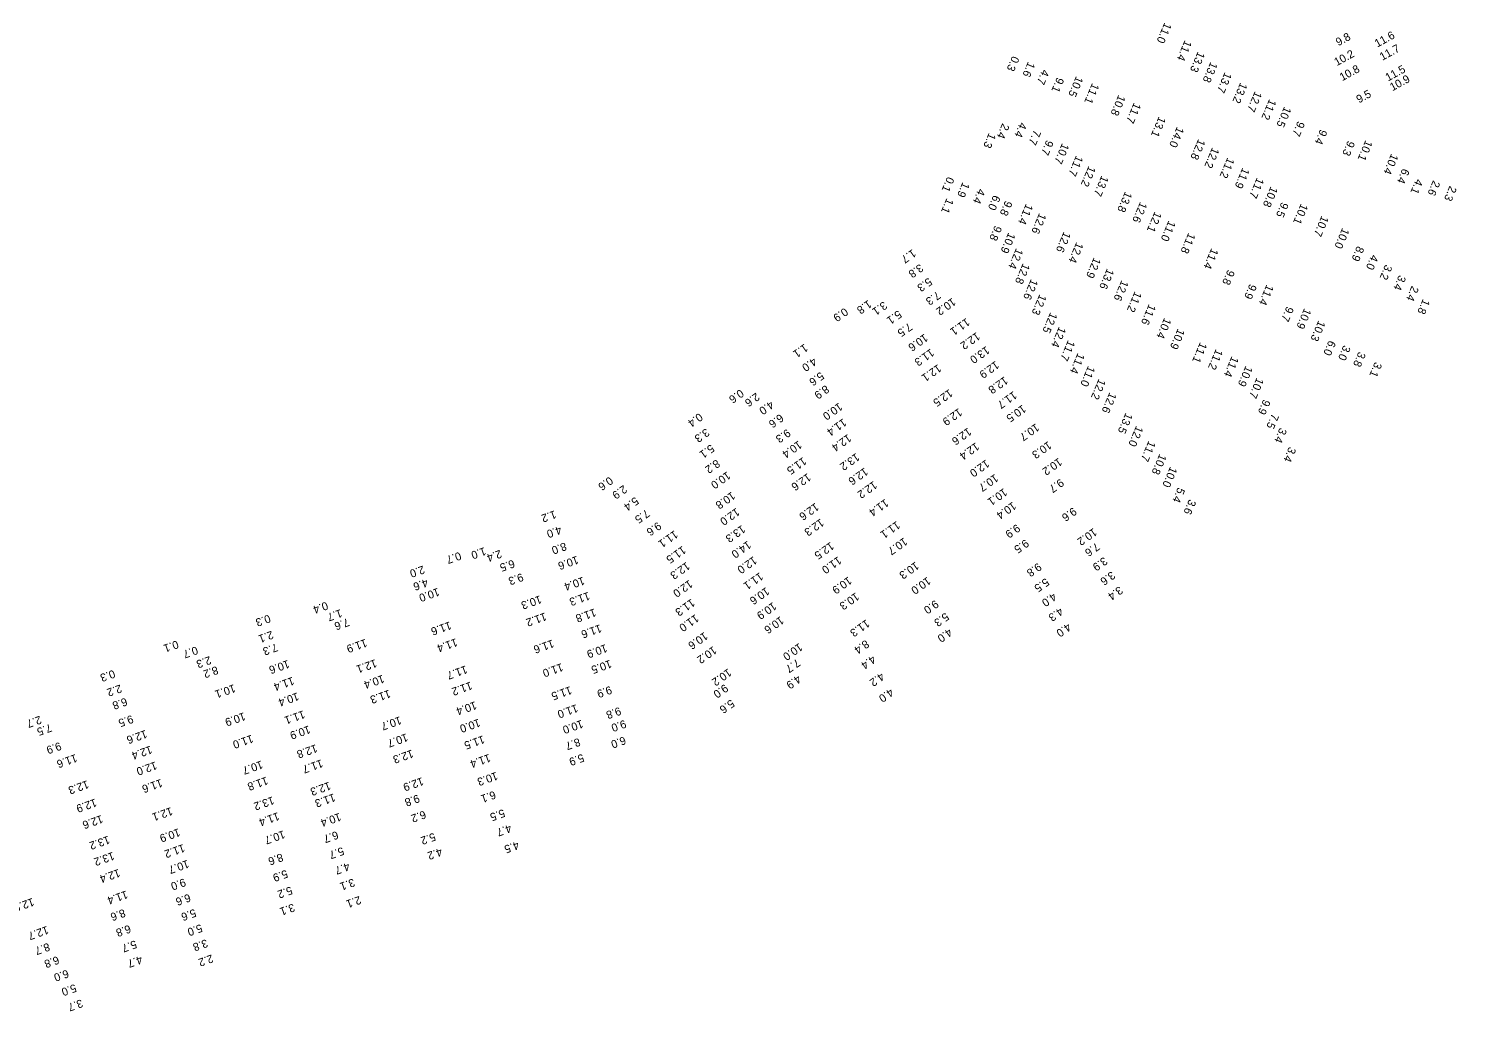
# Model space of a CAD drawing. Extents: x 815385 to 820851, y 582449 to 604245.
# Drawn here: x 817257 to 818150, y 599658 to 600273 of the extents above; entities that cross this region are included whole.
import ezdxf

# ---------------------------------------------------------------- set-up
doc = ezdxf.new("R2010")
doc.units = 0
doc.layers.add('V-TOPO-SOUN-021909', color=7, linetype='Continuous')
doc.layers.add('V-TOPO-SOUN-022409', color=7, linetype='Continuous')

msp = doc.modelspace()

# ---------------------------------------------------------------- texts
at = {"layer": 'V-TOPO-SOUN-021909'}
for s, rotation, p in [('11.0 ', 246.933, (817967.27, 600276.69)), ('11.4 ', 246.933, (817979.92, 600265.64)), ('0.3', 246.933, (817872.11, 600255.81)), ('13.3 ', 246.933, (817988.1, 600258.56)), ('1.6', 246.933, (817881.99, 600252.18)), ('4.7', 246.933, (817890.89, 600247.45)), ('13.8 ', 246.933, (817996.04, 600252.1)), ('13.7 ', 246.933, (818004.9, 600245.63)), ('9.1', 246.933, (817900.08, 600242.54)), ('10.5 ', 246.933, (817912.05, 600243.17)), ('11.1 ', 246.933, (817922.07, 600238.81)), ('13.2 ', 246.933, (818014.63, 600239.16)), ('10.8 ', 246.933, (817938.49, 600231.42)), ('12.7 ', 246.933, (818023.74, 600233.75)), ('11.2 ', 246.933, (818032.75, 600228.85)), ('11.7 ', 246.933, (817948.18, 600226.62)), ('10.5 ', 246.933, (818042.1, 600224.19)), ('2.4', 246.933, (817865.93, 600213.68)), ('4.4', 246.933, (817876.9, 600214.43)), ('13.1 ', 246.933, (817963.71, 600217.97)), ('14.0 ', 246.933, (817975.06, 600211.58)), ('9.7', 246.933, (818050.52, 600215.09)), ('9.4', 246.933, (818064.54, 600210)), ('1.3', 246.933, (817857.52, 600207.72)), ('7.7', 246.933, (817885.69, 600209.65)), ('9.7', 246.933, (817893.47, 600203.31)), ('10.7 ', 246.933, (817903.28, 600201.27)), ('12.8 ', 246.933, (817988.38, 600203.88)), ('9.3', 246.933, (818081.8, 600202.92)), ('10.1 ', 246.933, (818092.86, 600203.17)), ('11.7 ', 246.933, (817912.05, 600193.59)), ('12.2 ', 246.933, (817997.1, 600198.63)), ('11.2 ', 246.933, (818006.61, 600192.34)), ('10.4 ', 246.933, (818108.96, 600194.73)), ('12.2 ', 246.933, (817919.85, 600187.06)), ('11.9 ', 246.933, (818016.02, 600185.92)), ('6.4', 246.933, (818115.98, 600185.54)), ('0.1', 246.933, (817831.5, 600180.36)), ('1.9', 246.933, (817841.11, 600176.95)), ('13.7 ', 246.933, (817927.92, 600181.02)), ('11.7 ', 246.933, (818025.04, 600179.75)), ('10.8 ', 246.933, (818033.64, 600174.25)), ('4.1', 246.933, (818124.41, 600179.03)), ('2.6', 246.933, (818135.1, 600178.03)), ('2.3', 246.933, (818145.44, 600174.65)), ('1.1', 246.933, (817831.11, 600166.89)), ('4.4', 246.933, (817850.93, 600172.96)), ('6.0', 246.933, (817860.38, 600168.89)), ('9.8', 246.933, (817867.77, 600165.46)), ('13.8 ', 246.933, (817942.67, 600171.07)), ('11.4 ', 246.933, (817880.72, 600163.43)), ('12.6 ', 246.933, (817888.99, 600157.6)), ('12.6 ', 246.933, (817952.05, 600164.59)), ('12.1 ', 246.933, (817961.14, 600158.53)), ('9.5', 246.933, (818040.38, 600164.46)), ('10.1 ', 246.933, (818052.53, 600163.53)), ('10.7 ', 246.933, (818065.42, 600155.92)), ('9.8', 246.933, (817861.22, 600149.86)), ('11.0 ', 246.933, (817969.83, 600152.92)), ('10.0 ', 246.933, (818078.37, 600148.33)), ('10.9 ', 246.933, (817869.74, 600145.43)), ('12.6 ', 246.933, (817904.33, 600145.99)), ('12.4 ', 246.933, (817912.18, 600139.39)), ('11.8 ', 246.933, (817982.23, 600145.27)), ('1.7', 215.121, (817809.75, 600134.98)), ('12.4 ', 246.933, (817874.56, 600135.63)), ('12.9 ', 246.933, (817923.13, 600129.88)), ('11.4 ', 246.933, (817996.54, 600135.63)), ('8.9', 246.933, (818087.59, 600137.02)), ('4.0', 246.933, (818096.58, 600131.68)), ('3.8', 215.121, (817814.31, 600125.79)), ('12.8 ', 246.933, (817878.77, 600126.22)), ('13.6 ', 246.933, (817931.36, 600122.93)), ('9.8', 246.933, (818006.75, 600122.24)), ('3.2', 246.933, (818105.17, 600125.44)), ('5.3', 215.121, (817819.77, 600117.17)), ('12.6 ', 246.933, (817883.86, 600116.42)), ('12.6 ', 246.933, (817940.4, 600115.67)), ('9.9', 246.933, (818020.47, 600113.36)), ('11.4 ', 246.933, (818031.06, 600112.95)), ('3.4', 246.933, (818113.74, 600118.86)), ('2.4', 246.933, (818121.75, 600112.14)), ('1.8', 215.121, (817782.04, 600103.2)), ('7.3', 215.121, (817825.12, 600108.72)), ('10.2 ', 215.121, (817834.62, 600104.56)), ('12.3 ', 246.933, (817889.17, 600106.86)), ('11.2 ', 246.933, (817948.68, 600108.64)), ('1.8', 246.933, (818128.75, 600103.94)), ('0.9', 215.121, (817767.27, 600098.4)), ('3.1', 215.121, (817791.69, 600102.35)), ('5.1', 215.121, (817800.76, 600096.79)), ('12.5 ', 246.933, (817895.91, 600095.54)), ('11.6 ', 246.933, (817957.51, 600100.68)), ('9.7', 246.933, (818043.58, 600099.32)), ('10.9 ', 246.933, (818054.59, 600098.15)), ('7.5', 215.121, (817807.39, 600089)), ('11.1 ', 215.121, (817843.37, 600091.94)), ('12.4 ', 246.933, (817901.32, 600086.6)), ('10.4 ', 246.933, (817967.12, 600092.17)), ('10.9 ', 246.933, (817975.56, 600085.4)), ('10.3 ', 246.933, (818063.41, 600090.45)), ('1.1', 215.121, (817742.2, 600075.84)), ('10.6 ', 215.121, (817817.18, 600082.1)), ('12.2 ', 215.121, (817849.79, 600083.14)), ('11.7 ', 246.933, (817906.98, 600078.17)), ('11.1 ', 246.933, (817989.48, 600076.88)), ('6.0', 246.933, (818069.95, 600078.08)), ('4.0', 215.121, (817747.75, 600067.3)), ('11.3 ', 215.121, (817821.1, 600072.84)), ('13.0 ', 215.121, (817855.75, 600074.37)), ('11.4 ', 246.933, (817913.03, 600070.15)), ('11.2 ', 246.933, (817999.36, 600072.64)), ('11.4 ', 246.933, (818009.25, 600068.11)), ('3.0', 246.933, (818079.14, 600075.04)), ('3.8', 246.933, (818088.56, 600071.02)), ('5.6', 215.121, (817752.25, 600058.32)), ('12.1 ', 215.121, (817825.6, 600063.06)), ('12.9 ', 215.121, (817861.65, 600065.13)), ('11.0 ', 246.933, (817919.56, 600062.14)), ('10.9 ', 246.933, (818017.95, 600062.13)), ('3.1', 246.933, (818098.73, 600064.58)), ('8.9', 215.121, (817755.45, 600050.04)), ('12.8 ', 215.121, (817867.22, 600055.46)), ('12.2 ', 246.933, (817926.18, 600054.03)), ('10.7 ', 246.933, (818024.87, 600054.76)), ('0.6', 215.121, (817702.11, 600047.46)), ('2.6', 215.121, (817712.03, 600045.27)), ('12.5 ', 215.121, (817832.7, 600047.54)), ('11.7 ', 215.121, (817872.82, 600046.22)), ('12.6 ', 246.933, (817932.92, 600045.57)), ('9.9', 246.933, (818029.03, 600041.18)), ('0.4', 215.121, (817676.46, 600032.63)), ('4.0', 215.121, (817720.98, 600040.28)), ('6.6', 215.121, (817726.98, 600032.06)), ('10.0 ', 215.121, (817763.8, 600039.04)), ('12.9 ', 215.121, (817838.6, 600035.6)), ('10.5 ', 215.121, (817878.5, 600037.77)), ('13.5 ', 246.933, (817942.97, 600032.76)), ('7.5', 246.933, (818034.36, 600032.33)), ('3.3', 215.121, (817680.64, 600022.97)), ('9.3', 215.121, (817731.35, 600022.67)), ('11.4 ', 215.121, (817766.36, 600029.18)), ('12.6 ', 215.121, (817844.41, 600023.44)), ('10.7 ', 215.121, (817886.77, 600026.09)), ('12.0 ', 246.933, (817949.58, 600024.65)), ('3.4', 246.933, (818039.29, 600023.48)), ('10.4 ', 215.121, (817738.47, 600015.32)), ('12.4 ', 215.121, (817769.38, 600019.43)), ('12.4 ', 215.121, (817849.26, 600014.22)), ('10.3 ', 215.121, (817894.51, 600014.93)), ('11.7 ', 246.933, (817957.33, 600015.3)), ('5.1', 215.121, (817683.71, 600013)), ('11.5 ', 215.121, (817741.33, 600005.03)), ('13.2 ', 215.121, (817774.47, 600007.55)), ('10.2 ', 215.121, (817901.04, 600004.57)), ('10.8 ', 246.933, (817964.13, 600007.09)), ('3.4', 246.933, (818045.03, 600011.54)), ('8.2', 215.121, (817687.23, 600003.56)), ('10.0 ', 215.121, (817693.88, 599996.07)), ('12.6 ', 215.121, (817779.78, 599998.47)), ('12.0 ', 215.121, (817855.64, 600003.48)), ('10.0 ', 246.933, (817970.82, 599999.14)), ('0.6', 215.121, (817620.4, 599992.89)), ('2.9', 215.121, (817629.17, 599987.55)), ('12.6 ', 215.121, (817744.14, 599994.96)), ('12.2 ', 215.121, (817785.45, 599990.1)), ('10.7 ', 215.121, (817861.17, 599994.44)), ('9.7', 215.121, (817902.13, 599991.57)), ('5.4', 215.121, (817636.45, 599980.2)), ('10.8 ', 215.121, (817696.79, 599983.45)), ('11.4 ', 215.121, (817792.65, 599978.89)), ('10.1 ', 215.121, (817866.77, 599985.6)), ('5.4', 246.933, (817975.64, 599986.2)), ('3.6', 246.933, (817982.61, 599978.77)), ('1.2', 199.431, (817586.09, 599971.6)), ('7.5', 215.121, (817643.31, 599972.39)), ('12.0 ', 215.121, (817699.58, 599973.26)), ('12.6 ', 215.121, (817749.06, 599976.43)), ('10.4 ', 215.121, (817872.33, 599977.1)), ('9.6', 215.121, (817910.11, 599973.65)), ('4.0', 199.431, (817589.44, 599961.85)), ('9.6', 215.121, (817650.61, 599964.57)), ('13.3 ', 215.121, (817703.1, 599962.55)), ('12.3 ', 215.121, (817752.25, 599966.6)), ('11.1 ', 215.121, (817799.82, 599965.06)), ('9.9', 215.121, (817874.81, 599963.18)), ('10.2 ', 215.121, (817922.83, 599960.69)), ('8.0', 199.431, (817592.54, 599951.61)), ('11.1 ', 215.121, (817661.03, 599959.27)), ('14.0 ', 215.121, (817706.73, 599952.75)), ('12.5 ', 215.121, (817758.53, 599952.03)), ('10.7 ', 215.121, (817804.4, 599954.79)), ('9.5', 215.121, (817880.28, 599953.72)), ('7.6', 215.121, (817924.51, 599951.65)), ('0.7', 199.431, (817526.7, 599945.71)), ('1.0', 199.431, (817542.23, 599948.59)), ('2.4', 199.431, (817552.03, 599946.93)), ('10.6 ', 199.431, (817600.02, 599943.15)), ('11.5 ', 215.121, (817665.98, 599949.5)), ('12.0 ', 215.121, (817710.37, 599943.05)), ('11.0 ', 215.121, (817763.21, 599943)), ('3.9', 215.121, (817929.36, 599942.63)), ('2.0', 199.431, (817503.87, 599937.08)), ('6.5', 199.431, (817560.14, 599940.85)), ('12.3 ', 215.121, (817668.48, 599939.53)), ('11.1 ', 215.121, (817714.27, 599933.03)), ('10.3 ', 215.121, (817811.61, 599939.66)), ('9.8', 215.121, (817888.18, 599938.98)), ('3.6', 215.121, (817934.19, 599933.69)), ('4.6', 199.431, (817506.04, 599928.95)), ('9.3', 199.431, (817565.54, 599932.4)), ('10.4 ', 199.431, (817603.87, 599930.11)), ('12.0 ', 215.121, (817670.21, 599928.31)), ('10.6 ', 215.121, (817718.14, 599923.73)), ('10.9 ', 215.121, (817769.65, 599930.36)), ('10.0 ', 215.121, (817819, 599930.17)), ('5.5', 215.121, (817892.94, 599929.44)), ('3.4', 215.121, (817938.93, 599924.37)), ('10.0 ', 199.431, (817513.16, 599923.15)), ('10.3 ', 199.431, (817576.98, 599918.46)), ('11.3 ', 199.431, (817607.15, 599920.65)), ('11.3 ', 215.121, (817671.59, 599916.56)), ('10.3 ', 215.121, (817774.24, 599920.43)), ('9.0', 215.121, (817823.86, 599915.77)), ('4.0', 215.121, (817897.6, 599920.33)), ('0.3', 199.431, (817407.54, 599906.5)), ('0.4', 199.431, (817443.46, 599914.57)), ('1.7', 199.431, (817452.31, 599909.85)), ('11.2 ', 199.431, (817580.06, 599907.73)), ('11.8 ', 199.431, (817611.02, 599910.31)), ('11.0 ', 215.121, (817674.06, 599906.83)), ('10.9 ', 215.121, (817722.53, 599914.42)), ('5.3', 215.121, (817830.33, 599907.85)), ('4.3', 215.121, (817901.79, 599911.13)), ('7.6', 199.431, (817456.75, 599904.23)), ('11.6 ', 199.431, (817520.61, 599902.17)), ('11.6 ', 199.431, (817614.49, 599900.37)), ('10.6 ', 215.121, (817727.21, 599905.57)), ('11.3 ', 215.121, (817780.83, 599903.6)), ('4.0', 215.121, (817832.42, 599898.04)), ('4.0', 215.121, (817906.69, 599901.36)), ('0.1', 199.431, (817350.05, 599890.35)), ('2.1', 199.431, (817409.34, 599896.33)), ('7.3', 199.431, (817412.08, 599888.48)), ('11.9 ', 199.431, (817467.9, 599891.27)), ('11.4 ', 199.431, (817524.42, 599891.63)), ('11.6 ', 199.431, (817584.72, 599890.87)), ('10.9 ', 199.431, (817617.99, 599887.99)), ('10.6 ', 215.121, (817679.65, 599895.74)), ('10.0 ', 215.121, (817738.88, 599888.82)), ('8.4', 215.121, (817780.41, 599890.8)), ('0.7', 199.431, (817362.19, 599886.69)), ('2.3', 199.431, (817370.53, 599880.51)), ('10.2 ', 215.121, (817685.2, 599886.87)), ('4.4', 215.121, (817784.66, 599881.17)), ('0.3', 199.431, (817310.44, 599871.96)), ('8.2', 199.431, (817374.85, 599874.27)), ('10.6 ', 199.431, (817419.42, 599878.11)), ('12.1 ', 199.431, (817474, 599878.57)), ('11.7 ', 199.431, (817530.58, 599874.67)), ('11.0 ', 199.431, (817590.43, 599876.09)), ('10.5 ', 199.431, (817620.76, 599878.19)), ('10.2 ', 215.121, (817694.48, 599872.9)), ('7.7', 215.121, (817737.43, 599879.05)), ('2.2', 199.431, (817314.64, 599862.76)), ('10.1 ', 199.431, (817385.68, 599862.93)), ('11.4 ', 199.431, (817422.36, 599867.54)), ('10.4 ', 199.431, (817478.7, 599868.82)), ('11.2 ', 199.431, (817533.61, 599864.55)), ('11.5 ', 199.431, (817595.85, 599861.7)), ('9.9', 199.431, (817620.85, 599861.89)), ('9.0', 215.121, (817692.37, 599863.19)), ('4.9', 215.121, (817737.97, 599868.87)), ('4.2', 215.121, (817790.04, 599870.44)), ('6.8', 199.431, (817318.06, 599854.58)), ('10.4 ', 199.431, (817425.29, 599857.8)), ('11.3 ', 199.431, (817482.65, 599859.5)), ('10.4 ', 199.431, (817536.39, 599852.27)), ('5.6', 215.121, (817696.28, 599853.59)), ('4.0', 215.121, (817795.77, 599860.56)), ('2.7', 199.431, (817264.46, 599843.23)), ('9.5', 199.431, (817321.82, 599843.71)), ('10.9 ', 199.431, (817391.93, 599845.41)), ('11.1 ', 199.431, (817429.08, 599846.61)), ('11.0 ', 199.431, (817599.68, 599850.42)), ('9.8', 199.431, (817626.57, 599848.71)), ('7.5', 199.431, (817270.89, 599838.25)), ('12.6 ', 199.431, (817330.45, 599834.38)), ('10.9 ', 199.431, (817432.49, 599837.15)), ('10.7 ', 199.431, (817489.42, 599842.88)), ('10.0 ', 199.431, (817538.65, 599841.38)), ('10.0 ', 199.431, (817602.93, 599840.67)), ('9.0', 199.431, (817629.8, 599840.68)), ('9.9', 199.431, (817276.83, 599826.82)), ('11.0 ', 199.431, (817396.81, 599831.41)), ('12.8 ', 199.431, (817436.82, 599825.39)), ('10.7 ', 199.431, (817493.42, 599832.23)), ('11.5 ', 199.431, (817541.37, 599830.95)), ('8.7', 199.431, (817601.13, 599829.35)), ('6.0', 199.431, (817629.61, 599830.38)), ('11.6 ', 199.431, (817286.77, 599819.31)), ('12.4 ', 199.431, (817333.6, 599824.57)), ('12.3 ', 199.431, (817496.88, 599822.09)), ('11.4 ', 199.431, (817545.11, 599819.37)), ('5.9', 199.431, (817603.45, 599819.47)), ('12.0 ', 199.431, (817336.61, 599814.68)), ('10.7 ', 199.431, (817402.79, 599815.22)), ('11.7 ', 199.431, (817440.33, 599815.99)), ('10.3 ', 199.431, (817549.56, 599808.15)), ('12.3 ', 199.431, (817294.01, 599802.89)), ('11.6 ', 199.431, (817340.09, 599803.74)), ('11.8 ', 199.431, (817405.97, 599805.17)), ('12.3 ', 199.431, (817445.23, 599801.98)), ('12.9 ', 199.431, (817503.23, 599804.79)), ('12.9 ', 199.431, (817298.97, 599791.45)), ('13.2 ', 199.431, (817409.87, 599792.86)), ('11.3 ', 199.431, (817448.11, 599794.71)), ('9.8', 199.431, (817500.72, 599794.09)), ('6.1', 199.431, (817548.3, 599796.35)), ('12.6 ', 199.431, (817302.87, 599781.22)), ('12.1 ', 199.431, (817346.42, 599786.13)), ('11.4 ', 199.431, (817413.13, 599782.93)), ('10.4 ', 199.431, (817451.65, 599782.55)), ('6.2', 199.431, (817504.68, 599784.04)), ('5.5', 199.431, (817554.01, 599784.91)), ('10.9 ', 199.431, (817351.1, 599772.89)), ('4.7', 199.431, (817558.17, 599775.39)), ('13.2 ', 199.431, (817307.14, 599768.25)), ('11.2 ', 199.431, (817354.04, 599763.06)), ('10.7 ', 199.431, (817416.66, 599771.65)), ('6.7', 199.431, (817449.95, 599771.25)), ('5.2', 199.431, (817510.69, 599770.14)), ('4.5', 199.431, (817562.92, 599764.83)), ('13.2 ', 199.431, (817310.04, 599758.15)), ('8.6', 199.431, (817415.42, 599757.29)), ('5.7', 199.431, (817453.49, 599761.22)), ('4.2', 199.431, (817514.9, 599760.72)), ('12.4 ', 199.431, (817313.62, 599747.52)), ('10.7 ', 199.431, (817356.64, 599753.19)), ('5.9', 199.431, (817418.32, 599747)), ('4.7', 199.431, (817457.09, 599751.55)), ('9.0', 199.431, (817354.59, 599741.66)), ('5.2', 199.431, (817421.21, 599736.62)), ('3.1', 199.431, (817460.24, 599741.55)), ('12.9 ', 199.431, (817259.85, 599729.39)), ('11.4 ', 199.431, (817318.38, 599734.03)), ('6.6', 199.431, (817357.62, 599732.04)), ('2.1', 199.431, (817464.16, 599730.61)), ('8.6', 199.431, (817316.86, 599722.51)), ('5.6', 199.431, (817361.04, 599722.55)), ('3.1', 199.431, (817422.69, 599725.88)), ('12.7 ', 199.431, (817268.88, 599711.86)), ('6.8', 199.431, (817320.27, 599712.61)), ('5.0', 199.431, (817364.94, 599713.05)), ('8.7', 199.431, (817269.64, 599701.32)), ('5.7', 199.431, (817323.95, 599702.94)), ('3.8', 199.431, (817368.34, 599703.6)), ('6.8', 199.431, (817275.48, 599693.11)), ('4.7', 199.431, (817327.48, 599693.34)), ('2.2', 199.431, (817371.79, 599694.04)), ('6.0', 199.431, (817281.5, 599684.64)), ('5.0', 199.431, (817286.27, 599675.61)), ('3.7', 199.431, (817290.29, 599666.06))]:
    msp.add_text(s, height=5, rotation=rotation, dxfattribs=at).set_placement(p)
at = {"layer": 'V-TOPO-SOUN-022409'}
for s, p in [('9.8', (818075.86, 600261.53)), ('11.6 ', (818100.17, 600260.7)), ('11.7 ', (818103.31, 600252.44)), ('10.2 ', (818074.87, 600249.08)), ('10.8 ', (818078.26, 600239.66)), ('11.5 ', (818106.87, 600239.49)), ('10.9 ', (818109.66, 600233.42)), ('9.5', (818088.73, 600225.81))]:
    msp.add_text(s, height=5, rotation=28.553, dxfattribs=at).set_placement(p)

doc.saveas('drawing.dxf')
